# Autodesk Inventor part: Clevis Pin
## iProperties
Author: cdotson
Shininess: 25.0
PropertySet Name: _Private Model Information
Created: 2001-02
Part Number: Clevis Pin
Document SubType Name: Modeling
Designer: cdotson
Material: Steel, Mild
Control State: 0
Master: False
Checked Out: False
PropertySet Name: Design Tracking Control
Density: 7.86
Volumn: 0.32621344462346646
Area: 3.7458813763301206
PropertySet Name: Model Information
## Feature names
1. Revolution1
2. Extrusion1
